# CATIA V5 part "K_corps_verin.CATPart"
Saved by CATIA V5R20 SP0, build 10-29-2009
Part number: corps_verin
Publications: "Corps principal", "Plan.2", "Plan.4", "Point.2"
Bounding box of the stored display mesh (mm): x -35 to 35, y -312.544 to -85.001, z 292.264 to 564.993
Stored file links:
  G:\Khaled_CFAO_2011\ST2M\ST2M_GR2\echouteau\Khaled\CAD_ThinkMotion\K_corps_verin.CATPart
  F:\2A\Proj Think Motion\trainv3\Version3\sql_general.CATProduct
  G:\Khaled_CFAO_2011\ST2M\ST2M_GR2\echouteau\Khaled\CAD_ThinkMotion\K_tige_verin.CATPart
  G:\Khaled_CFAO_2011\ST2M\ST2M_GR2\echouteau\Khaled\CAD_ThinkMotion\K_corps.CATPart
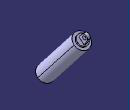
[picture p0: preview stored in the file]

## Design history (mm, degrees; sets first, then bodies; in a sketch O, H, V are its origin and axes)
Set1
  Line1 "direction_verin": linked copy from another document
  Point1: linked copy from another document
  Point2: linked copy from another document
  Plane1 "Plan_bout_tige": linked copy from another document
Body1 (main body)
  Point3 "point_longueur_corps_verin": type OnCurve, Support Line1, Length 300
  Line2 "corps_verin": type PtPt, FirstPoint Point1, SecondPoint Point3
  Plane2 "Plan_pivot_corps_verin_corps": type Normal, Curve Line2, RefPoint Point1
  Plane3 "Plan_bout_corps": type OffsetPt, RefPlane Plane2, RefPoint Point3
  Plane4: type 1Line1Pt, RefPoint Point2, Line Line1
  Plane5: type OffsetPt, RefPlane Plane4, RefPoint Point3
  Line3: type PtDir, RefPoint Point1, Direction yz-plane, Start 0, End -185
  Plane6: type OffsetPt, RefPlane yz-plane, RefPoint vertex of Line3
  Sketch1 on Plane3, origin (0, 41.4527, 58.0953), H (1, 0, 0), V (0, -0.7872, 0.6167)
    circle A1 centre (0, 414.7036) radius 35
    point P1 (0, 414.7036)
    reference projected point E1 (0, 414.7036) from Point3
    coincidence: E1 P1
  Pad1: profile Sketch1, direction (0, -0.6167, -0.7872), up to Plane2, offset -30
  Point4: stored without definition
  Sketch2 on start face of Pad1, origin (0, -264.2129, 297.5484), H (1, 0, 0), V (0, -0.7872, 0.6167)
    point P1 (0, 26.4134)
    construction circle A1 centre (0, 26.4134) radius 38.2884
    point P2 (0, 26.4134)
    reference projected point E1 (0, 26.4134) from Point1
    reference projected point E2 (0, 26.4134) from Point4
    coincidence: P2 E1, P1 E2
  Hole1: placed by Sketch2, at (0, -285.0058, 313.8372) direction (0, 0.6167, 0.7872), diameter 50, depth 260
  Sketch3 on end face of Pad1, origin (0, 191.6852, 283.3896), H (-1, 0, 0), V (0, -0.7872, 0.6167)
    circle A1 centre (0, 394.0322) radius 23.3238
    point P1 (0, 394.0322)
    reference projected point E1 (0, 394.0322) from Point1
    coincidence: P1 E1
  Pad2: profile Sketch3, direction (0, 0.6167, 0.7872), length 8
  Sketch4 on yz-plane, origin (0, 0, 0), H (0, 1, 0), V (0, 0, 1)
    point P1 (-124.8304, 541.5049)
    point P2 (-104.8217, 564.2039)
    reference projected point E1 (-124.8304, 541.5049) from vertex [element of Sketch5 | element of Sketch5]
    point P3 (-124.8304, 541.5049)
    point P4 (-162.9761, 469.61)
    reference projected line E2 (-433.524, 124.2515) -> (-100, 550) from Line1
    reference projected line E3 (-433.524, 124.2515) -> (-100, 550) from edge of Line1
    point P7 (-85.0548, 548.7189)
    point P8 (-162.9761, 469.61)
    arc A1 centre (-100, 550) radius 15 from (-104.8217, 564.2039) to (-85.0548, 548.7189) cw
    point P9 (-100, 550)
    reference projected point E4 (-100, 550) from Point1
    line L1 (-85.0548, 548.7189) -> (-100, 522)
    line L2 (-104.8217, 564.2039) -> (-129, 545)
    line L3 (-129, 545) -> (-100, 522)
    coincidence: P1 E1, P3 P1, P4 E2, P9 E4, P4 P8
    symmetry: P2 P7 E3, P4 P8 E3
  Sketch5 on end face of Pad2, origin (0, 196.1365, 290.065), H (-1, 0, 0), V (0, -0.7872, 0.6167)
    line L1 (0, 407.7277) -> (-6.5, 407.7277)
    point P1 (0, 407.7277)
    point P2 (-6.5, 407.7277)
    line L2 (-6.5, 407.7277) -> (-6.5, 367.7277)
    point P3 (-6.5, 367.7277)
    line L3 (-6.5, 367.7277) -> (0, 367.7277)
    point P4 (0, 367.7277)
    reference intersected line E1 through (0, 0) direction (0, 1) from Plane5
    point P7 (0, 367.7277)
    point P8 (6.5, 367.7277)
    line L4 (6.5, 367.7277) -> (0, 367.7277)
    point P9 (6.5, 407.7277)
    line L5 (6.5, 407.7277) -> (6.5, 367.7277)
    point P10 (0, 407.7277)
    line L6 (0, 407.7277) -> (6.5, 407.7277)
    distance P2 P9 = 13
    length L5 = 40
    coincidence: P1 V, P4 V, P1 P10, P4 P7
    horizontal: L1 H, L3 H
    vertical: L2 V
    symmetry: P4 P7 E1, P3 P8 E1, L3 L4 E1, P2 P9 E1, L2 L5 E1, P1 P10 E1, L1 L6 E1
  SolidCombine1: FirstComponentProfile Sketch4, FirstComponentDirection Sketch4, SecondComponentProfile Sketch5, SecondComponentDirection Sketch5
  Sketch6 on face of SolidCombine1 from Sketch5.L2, origin (6.5, -91.2821, 554.4211), H (0, 1, 0), V (0, 0, 1)
    point P1 (-8.7179, -4.4211)
    reference projected arc E1 centre (-8.7179, -4.4211) radius 15 from (5.8994, -7.7878) to (-18.5333, 6.9216) ccw from edge [face of SolidCombine1 from Sketch4.A1 | face of SolidCombine1 from Sketch5.L2]
    concentricity: P1 E1
  Hole2: placed by Sketch6, at (6.5, -100, 550) direction (-1, 0, 0), diameter 15, up to face of SolidCombine1 from Sketch5.L5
